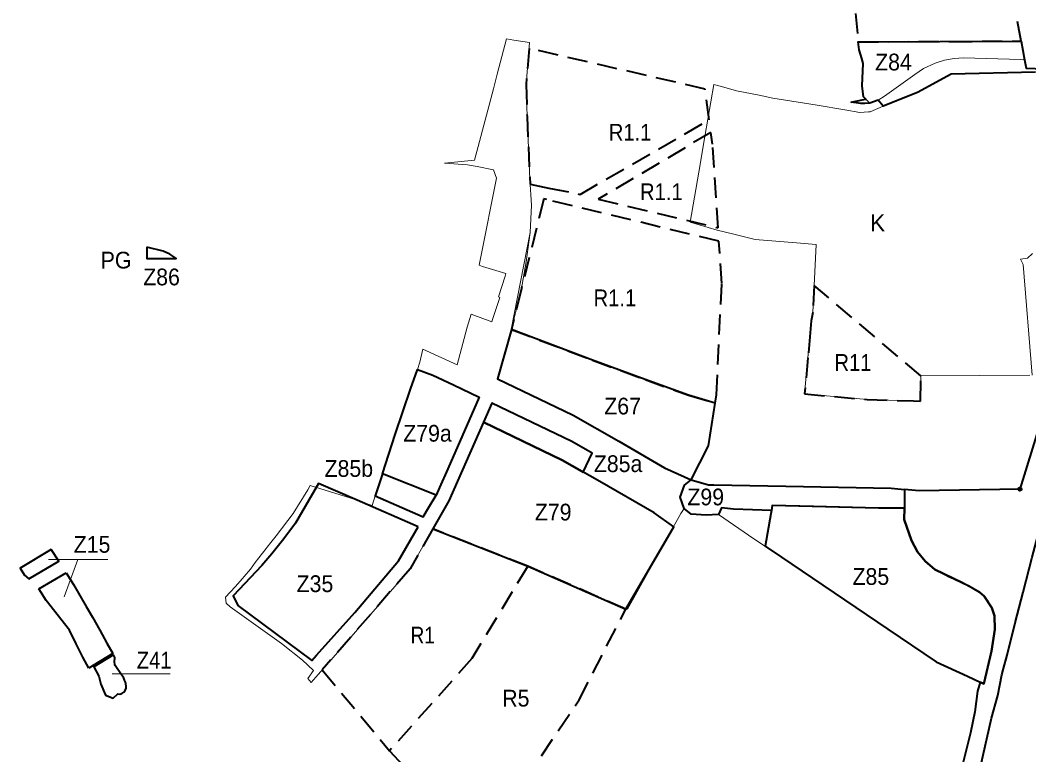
# Model space of a CAD drawing. Extents: x -650276 to -642489, y -1074311 to -1066658.
# Drawn here: x -646636 to -645192, y -1071749 to -1070697 of the extents above; entities that cross this region are included whole.
import ezdxf

# ---------------------------------------------------------------- set-up
doc = ezdxf.new("R2010")
doc.units = 0
doc.header["$LTSCALE"] = 9.6
doc.header["$PDMODE"] = 32
doc.header["$PDSIZE"] = 4.8
doc.linetypes.add('MEDIUM_DASHED', pattern=[4.5, 3, -1.5])
for name, color, linetype, lineweight in [('44', 7, 'Continuous', 40), ('45', 7, 'Continuous', 40), ('46', 7, 'Continuous', 13), ('47', 7, 'Continuous', 13), ('48', 7, 'Continuous', 13), ('60', 7, 'Continuous', 35), ('61', 7, 'MEDIUM_DASHED', 40), ('62', 7, 'Continuous', 35), ('63', 7, 'Continuous', 13)]:
    doc.layers.add(name, color=color, linetype=linetype, lineweight=lineweight)

msp = doc.modelspace()

# ---------------------------------------------------------------- linework, layer by layer
at = {"layer": '44'}
msp.add_line((-645369.665, -1071395.694), (-645370.24, -1071411.83), dxfattribs=at)
for points in [[(-645182, -1070771), (-645303, -1070774), (-645351, -1070800), (-645400.05, -1070819.84), (-645407.37, -1070810.95), (-645419.18, -1070815.44), (-645426.36, -1070815.78), (-645432.07, -1070816.05), (-645445.81, -1070814.06), (-645429.993, -1070810.647), (-645424.969, -1070809.563), (-645428.39, -1070806.09), (-645430, -1070790.68), (-645428.73, -1070758.67), (-645430.84, -1070751.43), (-645434.53, -1070738.77), (-645435.711, -1070727.497), (-645202.41, -1070726.571), (-645197.539, -1070753.128), (-645195.527, -1070765.319), (-645156.988, -1070766.884)], [(-645078.23, -1070915.65), (-645092.67, -1070979.52), (-645176.14, -1071277.26), (-645204.341, -1071368.19)], [(-645407.045, -1071395.646), (-645499.65, -1071393.3), (-645558.872, -1071391.801), (-645560.11, -1071398.7), (-645614.201, -1071396.844), (-645631.44, -1071394.9), (-645635.795, -1071404.403), (-645653.742, -1071405.36), (-645675.177, -1071403.922), (-645685.098, -1071395.824), (-645690.677, -1071379.721), (-645684.785, -1071362.539), (-645674.947, -1071355.071), (-645650.28, -1071362.07), (-645642.431, -1071362.259), (-645539.738, -1071364.092)], [(-645539.738, -1071364.092), (-645388.619, -1071366.991), (-645369.696, -1071368.676)], [(-645369.67, -1071368.678), (-645369.665, -1071395.694), (-645407.045, -1071395.646)], [(-645204.341, -1071368.19), (-645348.55, -1071370.559), (-645369.67, -1071368.678)], [(-645222.48, -1071606.08), (-645211.27, -1071560.01), (-645199.61, -1071515.68), (-645186.67, -1071465.55), (-645175.06, -1071420.93), (-645167.58, -1071421.19), (-645167.37, -1071415.2), (-645163.56, -1071415.3), (-645164.76, -1071401.79), (-645166.34, -1071384.07)], [(-645560.94, -1071403.441), (-645569.07, -1071449.88), (-645545.817, -1071465.611)], [(-645370.24, -1071411.83), (-645369.665, -1071395.694), (-645407.045, -1071395.646), (-645558.872, -1071391.801), (-645560.11, -1071398.7), (-645560.94, -1071403.441)], [(-645370.24, -1071411.83), (-645359.64, -1071442), (-645351.06, -1071458.3), (-645340.16, -1071471.63), (-645326.29, -1071483.41), (-645286.62, -1071502.67), (-645278.52, -1071506.12)], [(-645326.29, -1071483.41), (-645340.16, -1071471.63), (-645351.06, -1071458.3), (-645359.64, -1071442), (-645370.24, -1071411.83)], [(-645545.817, -1071465.611), (-645501.37, -1071495.68), (-645393.34, -1071568.75)], [(-645279.531, -1071636.404), (-645261.094, -1071645.025), (-645256.02, -1071647.398), (-645244.81, -1071600.61), (-645240.26, -1071569.52), (-645240.82, -1071549.6), (-645244.4, -1071538.48), (-645255.51, -1071521.55), (-645262.36, -1071515.72), (-645286.62, -1071502.67), (-645326.29, -1071483.41)], [(-645278.52, -1071506.12), (-645262.36, -1071515.72), (-645255.51, -1071521.55), (-645244.4, -1071538.48), (-645240.82, -1071549.6), (-645240.26, -1071569.52), (-645244.81, -1071600.61), (-645256.02, -1071647.398), (-645261.094, -1071645.025)], [(-645393.34, -1071568.75), (-645324.17, -1071615.53), (-645279.531, -1071636.404)], [(-645347.551, -1072443.527), (-645347.677, -1072391.355), (-645346.62, -1072330.914), (-645343.458, -1072278.998), (-645339.908, -1072235.158), (-645335.367, -1072185.207), (-645325.498, -1072102.789), (-645309.01, -1071998.147), (-645285.617, -1071875.733), (-645244.798, -1071696.585), (-645235.793, -1071663.703), (-645230.436, -1071634.261), (-645227.905, -1071625.277), (-645222.48, -1071606.08)], [(-645261.094, -1071645.025), (-645264.841, -1071657.687), (-645269.077, -1071687.396), (-645274.868, -1071717.176), (-645286.175, -1071761.228), (-645300.076, -1071820.179), (-645313.153, -1071883.081)]]:
    msp.add_lwpolyline(points, dxfattribs=at)
for points in [[(-646454.59, -1071021.54), (-646454.59, -1071038), (-646412.54, -1071038.01), (-646415.61, -1071035.4), (-646421.58, -1071031.81), (-646430.91, -1071027.44)], [(-645829.706, -1071343.963), (-645816.714, -1071316.828), (-645846, -1071300), (-645960.34, -1071245.09), (-645972.422, -1071272.568), (-645859.986, -1071326.563)], [(-646117.031, -1071346.48), (-646127.301, -1071378.036), (-646058.719, -1071407.796), (-646051.148, -1071395.208), (-646040.084, -1071376.813)]]:
    msp.add_lwpolyline(points, close=True, dxfattribs=at)
msp.add_point((-645204.341, -1071368.19), dxfattribs=at)
at = {"layer": '45'}
msp.add_line((-646609.21, -1071510.98), (-646570, -1071488.38), dxfattribs=at)
msp.add_line((-646609.21, -1071510.98), (-646570, -1071488.38), dxfattribs=at)
for points in [[(-645674.947, -1071355.071), (-645650.09, -1071306.433), (-645640.737, -1071244.963), (-645678.86, -1071233.58), (-645741.09, -1071211.36), (-645816.47, -1071183.63), (-645932.502, -1071139.426), (-645952.419, -1071210.117), (-645844.079, -1071262.487), (-645778.69, -1071299.362), (-645713.428, -1071337.765)], [(-646067.097, -1071196.699), (-646044.944, -1071205.157), (-646015.387, -1071218.854), (-645978.403, -1071236.481), (-646023.652, -1071339.428), (-646035.241, -1071365.795), (-646040.084, -1071376.813), (-646117.031, -1071346.48), (-646098.66, -1071290.03), (-646076.713, -1071225.138)], [(-645768.62, -1071540.17), (-645699.825, -1071422.134), (-645728.054, -1071402.382), (-645806.036, -1071357.564), (-645859.986, -1071326.563), (-645972.422, -1071272.568), (-646022.073, -1071385.273), (-646044.948, -1071425.333), (-645909.13, -1071478.56)], [(-645768.62, -1071540.17), (-645699.825, -1071422.134), (-645728.054, -1071402.382), (-645806.036, -1071357.564), (-645859.986, -1071326.563), (-645972.422, -1071272.568), (-646022.073, -1071385.273), (-646044.948, -1071425.333), (-645909.13, -1071478.56)], [(-646066.165, -1071422.155), (-646153.5, -1071383.85), (-646208.577, -1071360.044), (-646241.68, -1071416.887), (-646258.487, -1071439.265), (-646275.615, -1071460.886), (-646289.976, -1071477.514), (-646330.914, -1071521.11), (-646324, -1071535), (-646217.978, -1071613.552), (-646211.407, -1071606.247), (-646156.471, -1071545.166), (-646094.063, -1071471.007)], [(-646066.165, -1071422.155), (-646153.5, -1071383.85), (-646208.577, -1071360.044), (-646241.68, -1071416.887), (-646258.487, -1071439.265), (-646275.615, -1071460.886), (-646289.976, -1071477.514), (-646330.914, -1071521.11), (-646324, -1071535), (-646217.978, -1071613.552), (-646211.407, -1071606.247), (-646156.471, -1071545.166), (-646094.063, -1071471.007)], [(-646591.65, -1071454.91), (-646635.79, -1071481.6), (-646629.37, -1071491.74), (-646623.18, -1071496.99), (-646580.58, -1071471.48)], [(-646591.65, -1071454.91), (-646635.79, -1071481.6), (-646629.37, -1071491.74), (-646623.18, -1071496.99), (-646580.58, -1071471.48)], [(-646502.39, -1071605.72), (-646530.27, -1071622.79), (-646522.99, -1071636.22), (-646520.32, -1071647.59), (-646513.43, -1071663.64), (-646502.53, -1071667.82), (-646496.06, -1071661.5), (-646492.89, -1071661.75), (-646490.07, -1071660.88), (-646487.36, -1071659.1), (-646485.29, -1071656.53), (-646484.15, -1071653.38), (-646483.97, -1071650.63), (-646484.38, -1071647.41), (-646485.2, -1071644.85), (-646486.31, -1071641.97), (-646487.56, -1071639.23), (-646497.83, -1071624.02), (-646499.829, -1071620.704), (-646500.289, -1071619.291), (-646500.83, -1071615.62), (-646500.34, -1071609.66)], [(-646502.39, -1071605.72), (-646530.27, -1071622.79), (-646522.99, -1071636.22), (-646520.32, -1071647.59), (-646513.43, -1071663.64), (-646502.53, -1071667.82), (-646496.06, -1071661.5), (-646492.89, -1071661.75), (-646490.07, -1071660.88), (-646487.36, -1071659.1), (-646485.29, -1071656.53), (-646484.15, -1071653.38), (-646483.97, -1071650.63), (-646484.38, -1071647.41), (-646485.2, -1071644.85), (-646486.31, -1071641.97), (-646487.56, -1071639.23), (-646497.83, -1071624.02), (-646499.829, -1071620.704), (-646500.289, -1071619.291), (-646500.83, -1071615.62), (-646500.34, -1071609.66)]]:
    msp.add_lwpolyline(points, close=True, dxfattribs=at)
for points in [[(-646570, -1071488.38), (-646559.53, -1071505.12), (-646550.23, -1071520.88), (-646541.14, -1071536.3), (-646532.04, -1071551.72), (-646521.8, -1071570.34), (-646511.47, -1071589.11), (-646503.31, -1071603.95), (-646531.2, -1071621.07), (-646537.28, -1071624.8)], [(-646570, -1071488.38), (-646559.53, -1071505.12), (-646550.23, -1071520.88), (-646541.14, -1071536.3), (-646532.04, -1071551.72), (-646521.8, -1071570.34), (-646511.47, -1071589.11), (-646503.31, -1071603.95), (-646531.2, -1071621.07), (-646537.28, -1071624.8)], [(-646537.28, -1071624.8), (-646545.89, -1071609.07), (-646555.78, -1071589.66), (-646565.17, -1071570.4), (-646598.63, -1071527.8), (-646609.21, -1071510.98)], [(-646537.28, -1071624.8), (-646545.89, -1071609.07), (-646555.78, -1071589.66), (-646565.17, -1071570.4), (-646598.63, -1071527.8), (-646609.21, -1071510.98)]]:
    msp.add_lwpolyline(points, dxfattribs=at)
at = {"layer": '46'}
for p, q in [((-646510.087, -1071469.269), (-646595.257, -1071469.269)), ((-646510.087, -1071469.269), (-646595.257, -1071469.269)), ((-646421.181, -1071633.007), (-646504.11, -1071633.007)), ((-646421.181, -1071633.007), (-646504.11, -1071633.007))]:
    msp.add_line(p, q, dxfattribs=at)
msp.add_lwpolyline([(-646510.087, -1071469.269), (-646553.419, -1071469.269), (-646572.844, -1071522.353)], dxfattribs=at)
msp.add_lwpolyline([(-646510.087, -1071469.269), (-646553.419, -1071469.269), (-646572.844, -1071522.353)], dxfattribs=at)
at = {"layer": '47'}
for points in [[(-645182, -1070771), (-645194.206, -1070771.303), (-645303, -1070774), (-645194.206, -1070771.303), (-645303, -1070774), (-645303, -1070774), (-645303, -1070774), (-645303, -1070774), (-645303, -1070774), (-645303, -1070774), (-645303, -1070774), (-645351, -1070800), (-645400.05, -1070819.84), (-645418.67, -1070827.72), (-645421.09, -1070827.89), (-645433.49, -1070828.76), (-645455.184, -1070825.042), (-645494.82, -1070818.45), (-645558.3, -1070808), (-645577.54, -1070804.13), (-645610.25, -1070797.55), (-645625, -1070793.5), (-645635.482, -1070790.628), (-645642.52, -1070788.7), (-645655.293, -1070863.28), (-645663.99, -1070914.06), (-645676.292, -1070985.89), (-645637.94, -1070997.4), (-645615.899, -1071002.753), (-645583.18, -1071010.7), (-645524.165, -1071015.506), (-645495.87, -1071017.81), (-645498.931, -1071076.631), (-645500.94, -1071115.24), (-645504.79, -1071144.18), (-645512.84, -1071231.9), (-645423.08, -1071239.85), (-645346.67, -1071242.07), (-645346.31, -1071206.07), (-645262.13, -1071205.432), (-645189.902, -1071204.885)], [(-645186.64, -1071204.86), (-645199.57, -1071046.58), (-645203.66, -1071038.81), (-645193.24, -1071037.31), (-645186.18, -1071030.83)]]:
    msp.add_lwpolyline(points, dxfattribs=at)
at = {"layer": '61'}
msp.add_line((-645909.13, -1071478.56), (-646044.948, -1071425.333), dxfattribs=at)
for points in [[(-645444.47, -1070643.85), (-645435.711, -1070727.497), (-645301.722, -1070726.965), (-645202.41, -1070726.571), (-645221.272, -1070623.729)], [(-646044.948, -1071425.333), (-646077.593, -1071482.499), (-646203.387, -1071627.322), (-646107, -1071743)]]:
    msp.add_lwpolyline(points, dxfattribs=at)
for points in [[(-645905.795, -1070931.641), (-645879, -1070937), (-645834, -1070946), (-645649.136, -1070839.223), (-645655.04, -1070795.257), (-645907.061, -1070736.979), (-645911.345, -1070788.463), (-645910.048, -1070834.649)], [(-645646.718, -1070857.232), (-645808, -1070953), (-645636.529, -1070993.874), (-645644.425, -1070874.306)], [(-645881.661, -1070953.494), (-645885.966, -1070952.452), (-645918.57, -1071083.449), (-645932.502, -1071139.426), (-645816.47, -1071183.63), (-645741.09, -1071211.36), (-645678.86, -1071233.58), (-645640.737, -1071244.963), (-645638.935, -1071233.122), (-645631.241, -1071073.956), (-645635.256, -1071013.15)], [(-645512.84, -1071231.9), (-645423.08, -1071239.85), (-645356.794, -1071241.776), (-645346.67, -1071242.07), (-645346.31, -1071206.07), (-645498.931, -1071076.631), (-645500.94, -1071115.24), (-645503.08, -1071126.98), (-645504.79, -1071144.18), (-645507.84, -1071180.326)], [(-645909.13, -1071478.56), (-645989, -1071611), (-646107, -1071743), (-645987.026, -1071872.902), (-645913.616, -1071786.041), (-645835.644, -1071670.191), (-645768.62, -1071540.17)]]:
    msp.add_lwpolyline(points, close=True, dxfattribs=at)
at = {"layer": '63'}
for points in [[(-646127.301, -1071378.036), (-646131.79, -1071391.83), (-646163.84, -1071380.66), (-646191.35, -1071372.15), (-646220.61, -1071363.16), (-646223.77, -1071369.24), (-646245.1, -1071403.04), (-646269.2, -1071435.22), (-646276.82, -1071444.86), (-646281.99, -1071451.4), (-646283.52, -1071453.34), (-646299.18, -1071473.54), (-646306.14, -1071482.86), (-646315.22, -1071493.44), (-646317.52, -1071496.12), (-646327.97, -1071508.29), (-646341.88, -1071522.81), (-646340.93, -1071531.64), (-646335.3, -1071537.05), (-646261.46, -1071589.38), (-646231.43, -1071613.06), (-646215.81, -1071627.86), (-646224.128, -1071639.584), (-646219.147, -1071645.065), (-646209.322, -1071634.004), (-646197.398, -1071620.579), (-646146.33, -1071561.722), (-646077.593, -1071482.499), (-646044.948, -1071425.333), (-646030.8, -1071431.15), (-645945.43, -1071463.62), (-645860.21, -1071499.986), (-645766.441, -1071539.999), (-645690.056, -1071403.266), (-645685.098, -1071395.824), (-645675.177, -1071403.922), (-645653.742, -1071405.36), (-645635.795, -1071404.403), (-645585.547, -1071439.64), (-645545.817, -1071465.611), (-645501.37, -1071495.68), (-645393.34, -1071568.75), (-645324.17, -1071615.53), (-645262.735, -1071644.258), (-645256.02, -1071647.398), (-645244.81, -1071600.61), (-645240.26, -1071569.52), (-645240.18, -1071558.89), (-645240.82, -1071549.6), (-645244.4, -1071538.48), (-645249.88, -1071528.19), (-645255.51, -1071521.55), (-645262.36, -1071515.72), (-645278.52, -1071506.12), (-645306.77, -1071494.16), (-645326.29, -1071483.41), (-645340.16, -1071471.63), (-645351.06, -1071458.3), (-645359.64, -1071442), (-645370.24, -1071411.83), (-645369.67, -1071368.678), (-645388.619, -1071366.991), (-645400.57, -1071366.762), (-645539.738, -1071364.092), (-645650.28, -1071362.07), (-645674.947, -1071355.071), (-645650.09, -1071306.433), (-645640.737, -1071244.963), (-645678.86, -1071233.58), (-645741.09, -1071211.36), (-645816.47, -1071183.63), (-645932.71, -1071139.493), (-645905.69, -1071000.578), (-645903.891, -1070961.723), (-645906.11, -1070924.449), (-645910.048, -1070834.649), (-645910.452, -1070820.25), (-645911.345, -1070788.463), (-645907.39, -1070740.933), (-645906.373, -1070728.716), (-645929.077, -1070725.07), (-645929.077, -1070725.07), (-645939.27, -1070723.43), (-645952.65, -1070773.98), (-645958.12, -1070794.72), (-645980.01, -1070877.28), (-645985.28, -1070897.13), (-646028.42, -1070901.38), (-645995.33, -1070903.68), (-645981.48, -1070906.35), (-645958.21, -1070910.84), (-645954.01, -1070922.8), (-645976.17, -1071035.39), (-645978.58, -1071047.68), (-645973.77, -1071049.17), (-645968.97, -1071050.66), (-645940.25, -1071059.59), (-645941.45, -1071063.3), (-645950.96, -1071092.8), (-645949.21, -1071093.62), (-645959.58, -1071125.39)], [(-645419.18, -1070815.44), (-645407.37, -1070810.95), (-645398.04, -1070805.44), (-645354.98, -1070774.28), (-645342.41, -1070765.76), (-645325.82, -1070757.94), (-645312.2, -1070753.77), (-645298.41, -1070751.48), (-645285.11, -1070750.69), (-645202.96, -1070752.89), (-645197.539, -1070753.128), (-645202.41, -1070726.571), (-645435.71, -1070727.497)], [(-645435.71, -1070727.497), (-645434.53, -1070738.77), (-645428.73, -1070758.67), (-645430, -1070790.68)], [(-645430, -1070790.68), (-645428.39, -1070806.09), (-645424.969, -1070809.563), (-645419.18, -1070815.44)], [(-645959.58, -1071125.39), (-645960.66, -1071128.71), (-645990.14, -1071117.76), (-645995.74, -1071136.22), (-646010.14, -1071190.08), (-646059.28, -1071167.97), (-646063.59, -1071186.33), (-646067.097, -1071196.699), (-646098.66, -1071290.03), (-646127.301, -1071378.036)]]:
    msp.add_lwpolyline(points, dxfattribs=at)
msp.add_lwpolyline([(-645932.71, -1071139.493), (-645930.943, -1071133.161), (-645918.57, -1071083.449), (-645911.474, -1071042.764), (-645905.69, -1071000.578)], close=True, dxfattribs=at)

# ---------------------------------------------------------------- texts
at = {"layer": '44', "width": 0.95}
for s, p in [('Z84', (-645411.663, -1070768.505)), ('Z84', (-645411.663, -1070768.505)), ('Z86', (-646459.658, -1071076.35)), ('Z86', (-646459.658, -1071076.35)), ('Z85b', (-646199.969, -1071350.698)), ('Z85a', (-645814.405, -1071343.847)), ('Z85a', (-645814.405, -1071343.847)), ('Z99', (-645680.485, -1071391.504)), ('Z99', (-645680.485, -1071391.504)), ('Z85', (-645444.048, -1071505.433)), ('Z85', (-645444.048, -1071505.433))]:
    msp.add_text(s, height=24, dxfattribs=at).set_placement(p)
at = {"layer": '46'}
for s, width, p in [('Z67', 0.95, (-645799.458, -1071261.304)), ('Z67', 0.95, (-645799.458, -1071261.304)), ('Z79a', 0.95, (-646087.322, -1071300.282)), ('Z79', 0.95, (-645898.897, -1071413.165)), ('Z79', 0.95, (-645898.897, -1071413.165)), ('Z15', 0.95, (-646559.155, -1071459.428)), ('Z15', 0.95, (-646559.155, -1071459.428)), ('Z35', 0.95, (-646239.99, -1071515.768)), ('Z35', 0.95, (-646239.99, -1071515.768)), ('Z41', 0.9, (-646468.869, -1071625.297)), ('Z41', 0.9, (-646468.869, -1071625.297))]:
    msp.add_text(s, height=24, dxfattribs=dict(at, width=width)).set_placement(p)
at = {"layer": '48'}
msp.add_text('K', height=24, dxfattribs=at).set_placement((-645418.824, -1070998.868))
msp.add_text('K', height=24, dxfattribs=at).set_placement((-645418.824, -1070998.868))
at = {"layer": '60', "width": 0.95}
msp.add_text('PG', height=24, dxfattribs=at).set_placement((-646520.539, -1071052.252))
msp.add_text('PG', height=24, dxfattribs=at).set_placement((-646520.539, -1071052.252))
at = {"layer": '62'}
for s, width, p in [('R1.1', 0.9, (-645792.947, -1070869.095)), ('R1.1', 0.9, (-645748.253, -1070954.32)), ('R1.1', 0.9, (-645814.758, -1071106.298)), ('R11', 0.9, (-645469.881, -1071198.853)), ('R1', 0.85, (-646076.842, -1071589.396)), ('R5', 0.95, (-645945.557, -1071679.725)), ('R5', 0.95, (-645945.557, -1071679.725))]:
    msp.add_text(s, height=24, dxfattribs=dict(at, width=width)).set_placement(p)

doc.saveas('drawing.dxf')
